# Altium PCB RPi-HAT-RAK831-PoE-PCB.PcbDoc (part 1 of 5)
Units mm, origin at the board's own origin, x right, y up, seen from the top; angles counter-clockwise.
Board outline 65 x 56 mm, 2 copper layers (Top Layer, Bottom Layer); 9 components, 14 nets, 9110 pads, 249 vias.
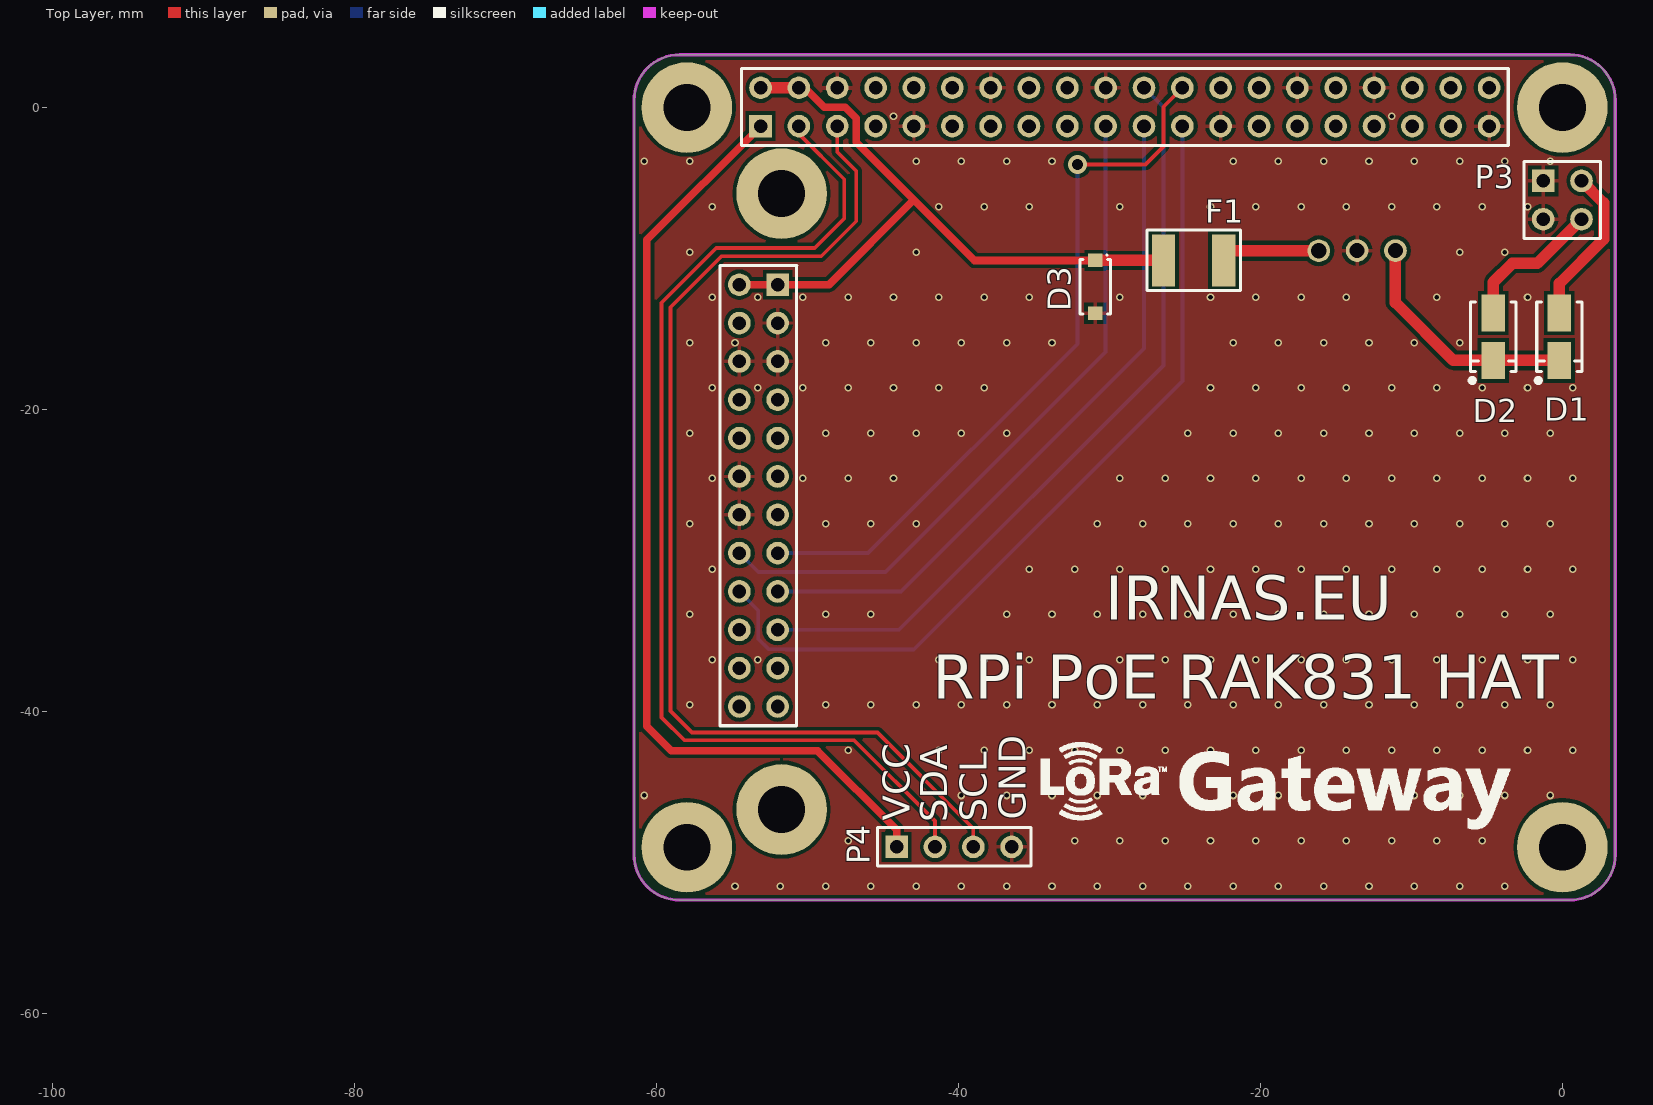
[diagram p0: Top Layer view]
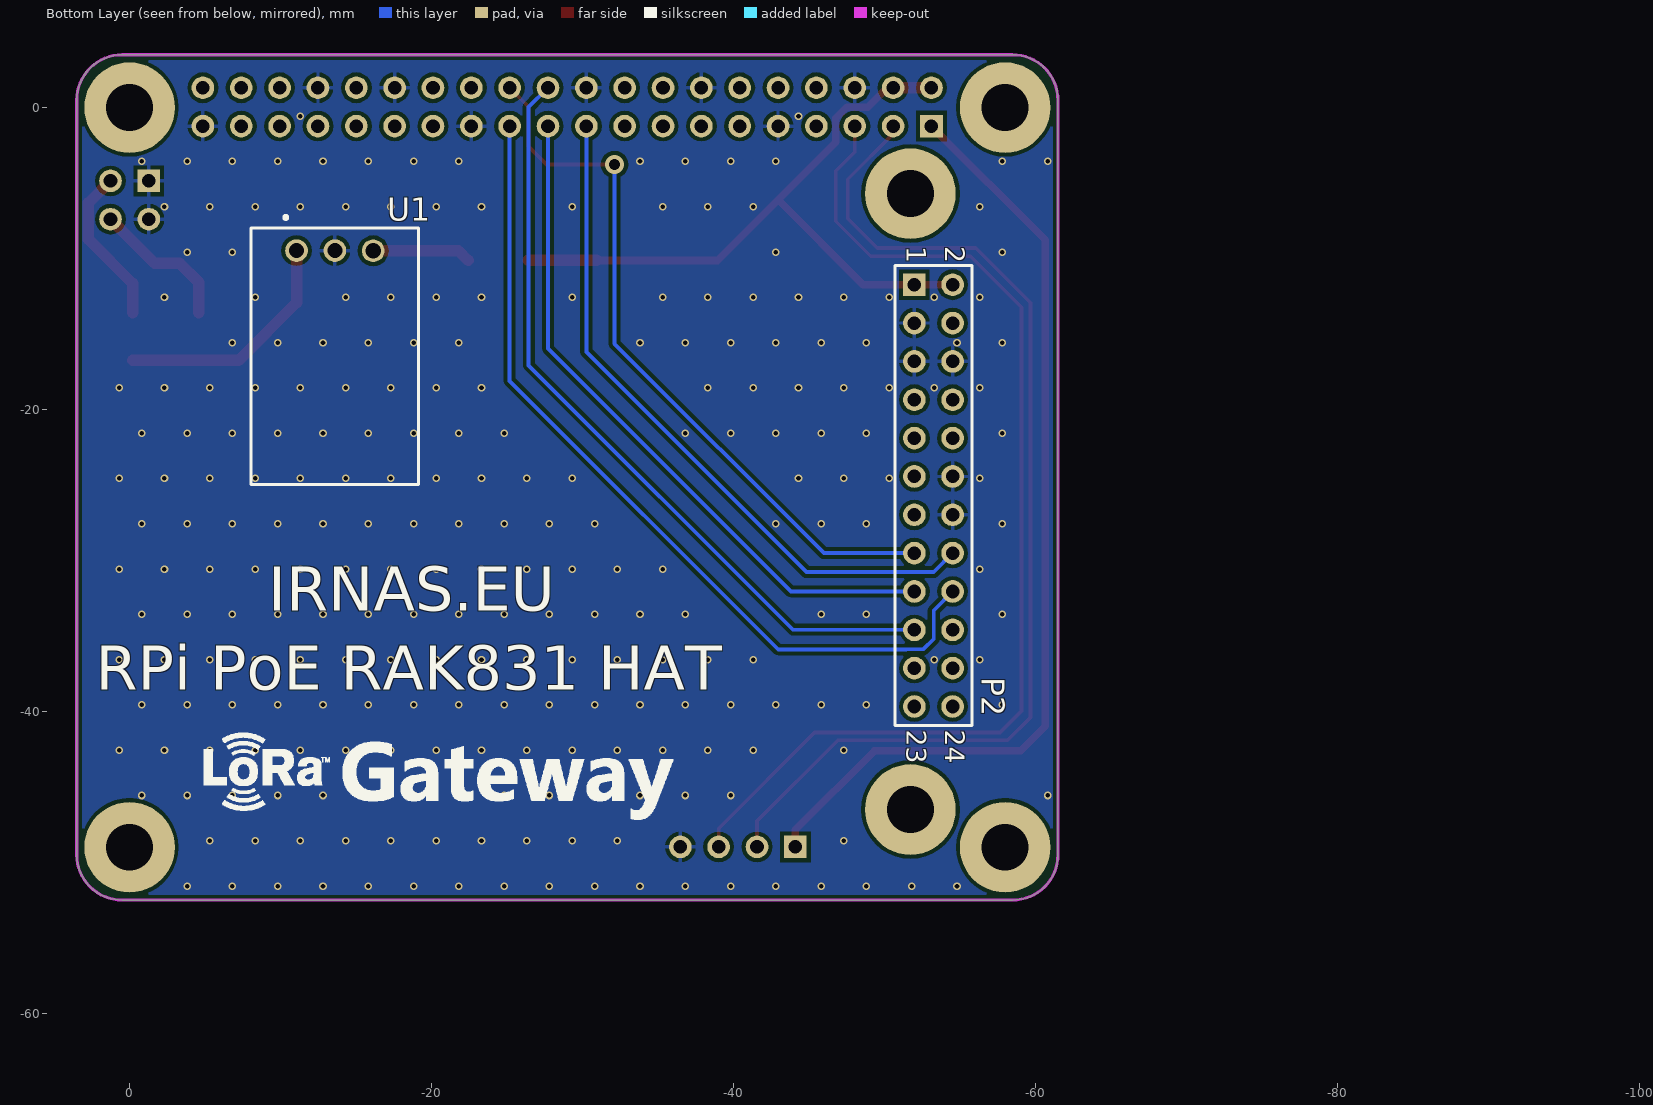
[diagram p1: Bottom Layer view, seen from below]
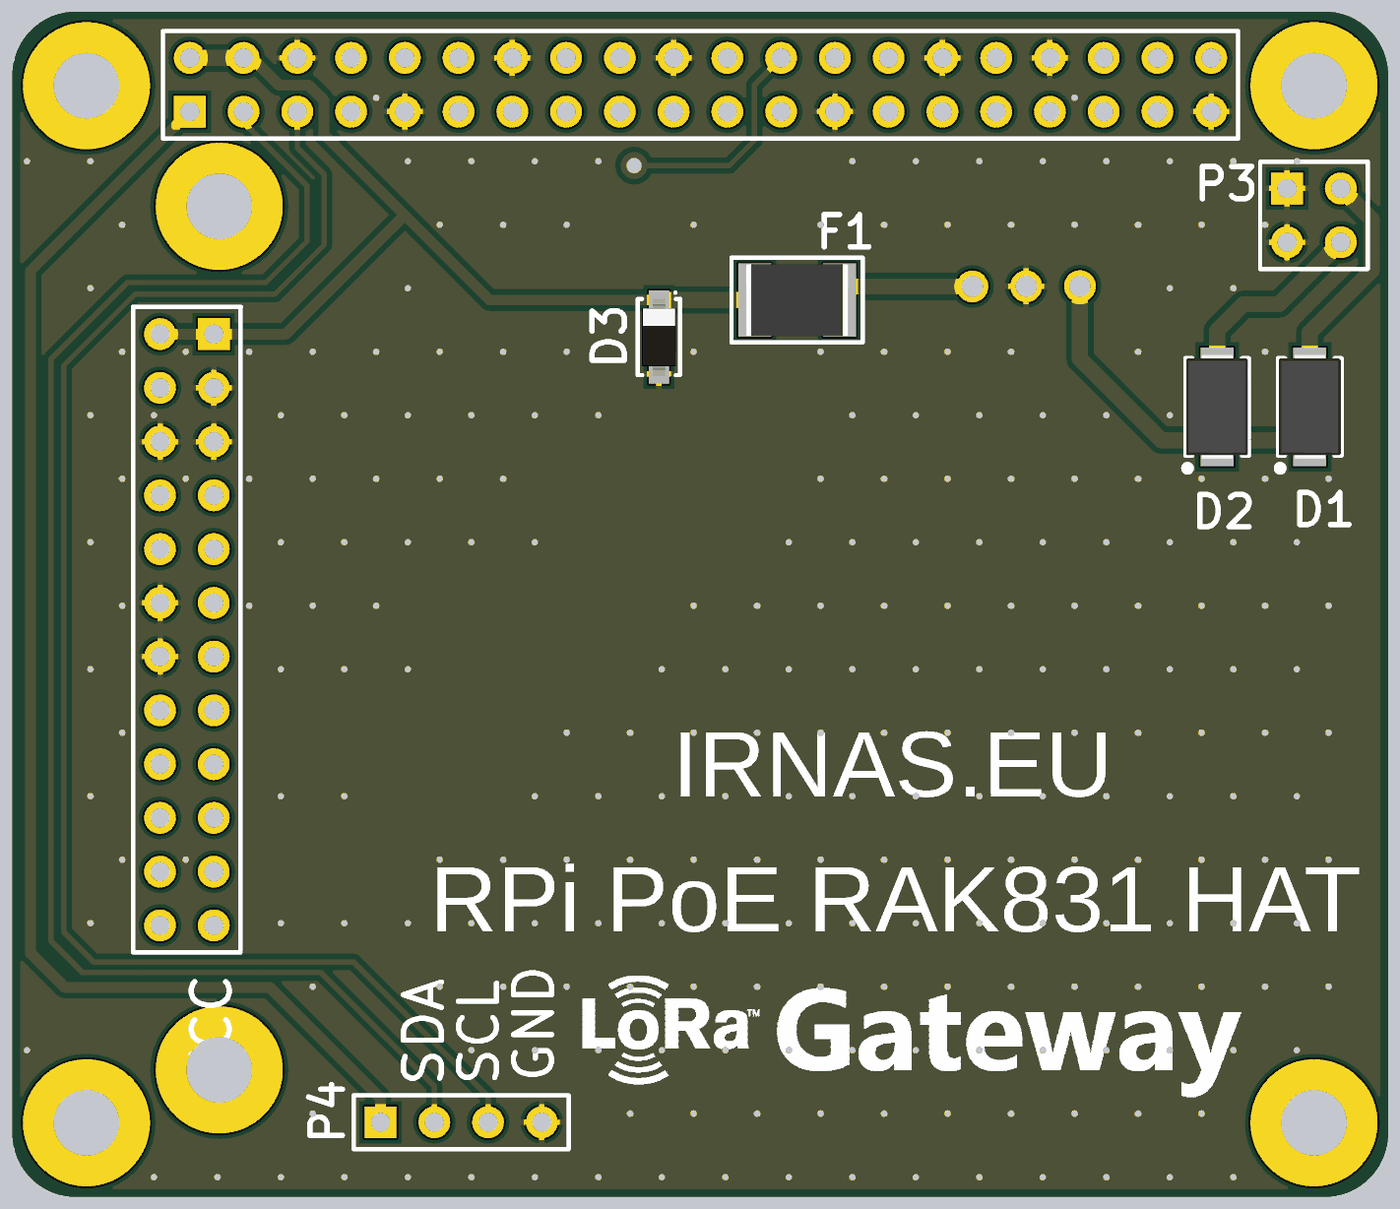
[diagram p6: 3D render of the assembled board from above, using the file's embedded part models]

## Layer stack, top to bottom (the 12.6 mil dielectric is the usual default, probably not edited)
Top Solder: solder mask 0.0102, Solder Resist, Dk 3.5
Top Layer: signal copper 0.0356
Dielectric 1: dielectric 0.32, FR-4, Dk 4.8
Bottom Layer: signal copper 0.0356
Bottom Solder: solder mask 0.0102, Solder Resist, Dk 3.5

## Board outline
-61.5,-49.5 ccw(c-58.5,-49.5) -58.5,-52.5 0.5,-52.5 ccw(c0.5,-49.5) 3.5,-49.5 3.5,0.5 ccw(c0.5,0.5) 0.5,3.5 -58.5,3.5 ccw(c-58.5,0.5) -61.5,0.5

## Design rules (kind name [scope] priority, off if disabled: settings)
BoardOutlineClearance [All] p1: gap=0.254 ignorepadtopadclearanceinfootprint=FALSE except(0: Arc-SplitContinuation Track-SplitContinuation SMDPad-SplitContinuation THPad-SplitContinuation Via-SplitContinuation Fill-SplitContinuation Poly-SplitContinuation Region-SplitContinuation Text-SplitContinuation)
Clearance [All] p1: gap=0.254 ignorepadtopadclearanceinfootprint=FALSE except(0: Arc-Hole Track-Hole SMDPad-Hole THPad-Hole Via-Hole Fill-Hole Poly-Hole Region-Hole Text-Hole)
ComponentClearance [All] p1: gap=0.01 collisioncheckmode=3 verticalgap=0.254 showdistances=FALSE
HoleSize [All] p1: absolutevalues=TRUE maxlimit=5 minlimit=0.025 maxpercent=80.000 minpercent=20.000
PolygonConnect PolygonConnect_t [IsVia vs OnLayer('Top Layer')] p1: connectstyle=Direct reliefconductorwidth=0.254 reliefentries=4 polygonreliefangle="90 Angle" airgapwidth=0.254
PolygonConnect PolygonConnect_b [IsVia vs OnLayer('Bottom Layer')] p2: connectstyle=Direct reliefconductorwidth=0.254 reliefentries=4 polygonreliefangle="90 Angle" airgapwidth=0.254
PolygonConnect [All] p3: connectstyle=Relief reliefconductorwidth=0.254 reliefentries=4 polygonreliefangle="90 Angle" airgapwidth=0.254
RoutingVias [All] p1: holewidth=0.711 width=1.27 viastyle="Through Hole" minholewidth=0.711 minwidth=1.27 maxholewidth=0.711 maxwidth=1.27
SolderMaskExpansion [All] p1: expansion=0.102
Width [All] p1: maxlimit=1.27 minlimit=0.254 preferedwidth=0.254 minimp=50.000000 maximp=50.000000 favimp=50.000000
28 further rules are at their usual default settings.

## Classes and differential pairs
component class PAGE2-RPI,RAK831,POWER: D1 D2 D3 F1 P2 P3 P4 U1

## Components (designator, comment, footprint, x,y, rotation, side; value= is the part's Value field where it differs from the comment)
D1 "MRA4007T3G" DIOM4326X24N_1 -0.2,-15.175 r90 top
D2 "MRA4007T3G" DIOM4326X24N_1 -4.575,-15.175 r90 top
D3 "BZT52C6V2" SOD123 -30.95,-11.875 r270 top
F1 "3A" Chip2PinSM127P600-8N -24.425,-10.125 r180 top
P1 "Header 20X2" HDR2X20 -53.118,-1.227 r0 top locked
P2 "Header 12X2" HDR2X12 -51.985,-11.735 r270 bottom
P3 "Header 2X2" HDR2X2 -1.275,-4.855 r270 top locked
P4 "Header 4" HDR1X4 -44.105,-48.975 r0 top
U1 "OKI-78SR-5" DC-DC -13.55,-23.975 r0 bottom

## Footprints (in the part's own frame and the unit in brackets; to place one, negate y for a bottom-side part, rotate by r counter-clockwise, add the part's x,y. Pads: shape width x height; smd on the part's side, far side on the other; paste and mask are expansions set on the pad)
Chip2PinSM127P600-8N [mm]
  rect 1.55x3.45 smd: 1(-2,0) 2(2,0)
  silkscreen extent -3.1,-2 3.1,2, body extent -2.41,-1.7 2.42,1.71, height 1.94
DC-DC [mm]
  round 1.501 hole 1: 1(2.49,-14.5) 2(-0.05,-14.5)
  round 1.5 hole 1: 3(-2.59,-14.49)
  silkscreen extent -5.6,-16.8 5.5,1, body extent -5.6,-15.98 5.49,0.96, height 7.6
DIOM4326X24N_1 [mm] "Molded Diode, 2-Leads, Body 4.31x2.60mm, IPC Medium Density"
  rect 2.45x1.55 smd: 1(-1.575,0) 2(1.575,0)
  silkscreen extent -3.05,-1.5 2.3,1.55, body extent -2.5,-1.46 2.51,1.46, height 2.41
HDR1X4 [mm] "Connector; Header; 4 Position"
  rect 1.5x1.5 hole 0.9: 1(0,0)
  round 1.5 hole 0.9: 2(2.54,0) 3(5.08,0) 4(7.62,0)
  silkscreen extent -1.27,-1.27 8.89,1.27
HDR2X2 [mm] "Connector; Header; 2x2 Position"
  rect 1.5x1.5 hole 0.9: 1(0,0)
  round 1.5 hole 0.9: 2(0,2.54) 3(2.54,0) 4(2.54,2.54)
  silkscreen extent -1.27,-1.27 3.81,3.81
HDR2X12 [mm] "Connector; Header; 12x2 Position"
  rect 1.5x1.5 hole 0.9: 1(0,0)
  round 1.5 hole 0.9: 2(0,2.54) 3(2.54,0) 4(2.54,2.54) 5(5.08,0) 6(5.08,2.54) 7(7.62,0) 8(7.62,2.54) 9(10.16,0) 10(10.16,2.54) 11(12.7,0) 12(12.7,2.54) 13(15.24,0) 14(15.24,2.54) 15(17.78,0) 16(17.78,2.54) 17(20.32,0) 18(20.32,2.54) 19(22.86,0) 20(22.86,2.54) 21(25.4,0) 22(25.4,2.54) 23(27.94,0) 24(27.94,2.54)
  silkscreen extent -1.27,-1.27 29.21,3.81
HDR2X20 [mm] "Connector; Header; 20x2 Position"
  rect 1.5x1.5 hole 0.9: 1(0,0)
  round 1.5 hole 0.9: 2(0,2.54) 3(2.54,0) 4(2.54,2.54) 5(5.08,0) 6(5.08,2.54) 7(7.62,0) 8(7.62,2.54) 9(10.16,0) 10(10.16,2.54) 11(12.7,0) 12(12.7,2.54) 13(15.24,0) 14(15.24,2.54) 15(17.78,0) 16(17.78,2.54) 17(20.32,0) 18(20.32,2.54) 19(22.86,0) 20(22.86,2.54) 21(25.4,0) 22(25.4,2.54) 23(27.94,0) 24(27.94,2.54) 25(30.48,0) 26(30.48,2.54) 27(33.02,0) 28(33.02,2.54) 29(35.56,0) 30(35.56,2.54) 31(38.1,0) 32(38.1,2.54) 33(40.64,0) 34(40.64,2.54) 35(43.18,0) 36(43.18,2.54) 37(45.72,0) 38(45.72,2.54) 39(48.26,0) 40(48.26,2.54)
  silkscreen extent -1.27,-1.27 49.53,3.81
SOD123 [mm] "SODFL, 2-Leads, Body 1.55x3.70mm, IPC Medium Density"
  rect 0.9x0.95 smd: 1(-1.75,0) 2(1.75,0)
  silkscreen extent -2.15,-1 1.8,1, body extent -1.85,-0.8 1.85,0.8, height 1.27

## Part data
D1 D2: "ON SEMICONDUCTOR - MRA4007T3G - DIODE, STANDARD, 1A, 1KV, SMA", Manufacturer="ON SEMICONDUCTOR", Supplier Part Number 1=1459137
D3: "DIODES INC. - BZT52C6V2 - DIODE, ZENER, 6.2V, 0.5W, SOD-123", Diode Case Style=SOD-123, Manufacturer="DIODES INC.", Operating Temperature Max=150, Operating Temperature Min=-65, Operating Temperature Range="-65°C to +150°C<!--FANDB--><div class{}\"features-and-benefits-container\"><div class{}\"features-and-benefits-desc-container\"><span class{}\"features-and-benefits-container-desc\">Zener Single Diode, 6.2 V, 500 mW, SOD-123, 6 %, 2 Pins, 150 °C</span></div><div class{}\"features-and-benefits-description\"><span class{}\"features-benefits-value\">The BZT52C6V2 is a surface mount Zener Diode with moulded plastic case, matte tin annealed over Alloy 42 lead frame (lead-free plating) terminals and cathode band polarity. It is ideally suited for automated assembly processes.</span></div><div class{}\"features-and-benefits-list\"><ul class{}\"features-and-benefits-list-list\"><li class{}\"features-and-benefits-list-item\">Planar die construction</li><li class{}\"features-and-benefits-list-item\">500mW Power dissipation</li><li class{}\"features-and-benefits-list-item\">General purpose, medium current</li><li class{}\"features-and-benefits-list-item\">Totally lead-free</li><li class{}\"features-and-benefits-list-item\">Halogen and antimony-free - Green device</li><li class{}\"features-and-benefits-list-item\">Qualified to AEC-Q101 standards for high reliability</li></ul></div><div class{}\"features-and-benefits-applications\"><ul class{}\"features-and-benefits-value\"><li class{}\"features-and-benefits-list-item\">Automation & Process Control</li></ul></div></div>", Power Dissipation Pd=500, Supplier Part Number 1=1902438, Zener Tolerance ±=6%, Zener Voltage Vz Typ=6.2
F1: library part "PTC FUSE 3A", "LITTELFUSE - MINISMDC150F/24-2 - POLYSWITCH, SMD, 1812, 1.5A", Manufacturer=LITTELFUSE, Manufacturer Part Number=MINISMDC150F/24-2, Supplier Part Number 1=1345929
P1: "Header, 20-Pin, Dual row"
P2: "Header, 12-Pin, Dual row"
P3: "Header, 2-Pin, Dual row"
P4: "Header, 4-Pin"
U1: library part OKI-78SR-5/1.5-W36H-C, "Non-Isolated DC/DC Converters 7.5W 24V 5Vout 1.5A Horizontal Mount", Case/Package=SIP, Current - Output 1=1.5A, Manufacturer=Murata, Max Input Voltage=36V, Max Operating Temperature=85°C, Max Power Dissipation=8W, Min Input Voltage=7V, Min Operating Temperature=-40°C, Nominal Input Voltage=24V, Output Power=7.5W, Output Voltage=5V, Package Quantity=100, Supplier Part Number 1=2766437

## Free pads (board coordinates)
  round 6 hole 3.1: 0(-58,-49) 0(-58,0) 0(-51.725,-46.5) 0(-51.725,-5.7) 0(0,-49) 0(0,0)
  round 0.008 on Mech16: 1(-98.413,-61.398) 1(-98.411,-61.431) 1(-98.409,-62.446) 1(-98.406,-62.479) 1(-98.402,-62.408) 1(-98.398,-61.456) 1(-98.393,-61.371) 1(-98.383,-62.504) 1(-98.373,-61.468) 1(-98.371,-62.392) 1(-98.358,-61.359) 1(-98.345,-62.504) 1(-98.343,-61.466) 1(-98.329,-62.395) 1(-98.322,-61.363) 1(-98.314,-61.453) 1(-98.313,-62.486) 1(-98.307,-62.422) 1(-98.302,-61.392) 1(-98.301,-62.454) 1(-98.3,-61.424) 1(-98.26,-62.529) 1(-98.26,-62.124) 1(-98.26,-62.04) 1(-98.259,-61.971) 1(-98.259,-61.491) 1(-98.258,-62.405) 1(-98.258,-61.933) 1(-98.258,-61.893) 1(-98.258,-61.629) 1(-98.257,-62.362) 1(-98.257,-62.179) 1(-98.256,-62.46) 1(-98.256,-62.219) 1(-98.256,-61.844) 1(-98.244,-61.454) 1(-98.233,-61.751) 1(-98.229,-61.727) 1(-98.223,-61.821) 1(-98.218,-61.707) 1(-98.217,-61.614) 1(-98.21,-61.577) 1(-98.205,-62.532) 1(-98.205,-62.02) 1(-98.203,-61.688) 1(-98.2,-61.339) 1(-98.187,-61.673) 1(-98.183,-61.394) 1(-98.18,-61.626) 1(-98.179,-61.932) 1(-98.179,-61.906) 1(-98.178,-62.239) 1(-98.171,-61.657) 1(-98.169,-61.878) 1(-98.164,-61.849) 1(-98.163,-61.735) 1(-98.162,-62.428) 1(-98.158,-62.233) 1(-98.154,-61.571) 1(-98.147,-61.808) 1(-98.146,-62.314) 1(-98.145,-61.526) 1(-98.139,-62.532) 1(-98.139,-62.442) 1(-98.136,-61.769) 1(-98.135,-61.945) 1(-98.135,-61.891) 1(-98.125,-61.591) 1(-98.122,-62.275) 1(-98.114,-61.87) 1(-98.105,-61.973) 1(-98.103,-61.582) 1(-98.102,-61.934) 1(-98.083,-61.57) 1(-98.079,-61.934) 1(-98.078,-62.533) 1(-98.075,-62.23) 1(-98.074,-62.263) 1(-98.071,-61.408) 1(-98.064,-62.122) 1(-98.064,-62.085) 1(-98.063,-62.102) 1(-98.063,-61.327) 1(-98.062,-61.559) 1(-98.057,-61.934) 1(-98.048,-62.097) 1(-98.04,-61.406) 1(-98.037,-62.311) 1(-98.035,-61.934) 1(-98.034,-61.555) 1(-98.034,-61.619) 1(-98.034,-61.329) 1(-98.031,-62.096) 1(-98.023,-62.535) 1(-98.014,-62.311) 1(-98.004,-62.107) 1(-97.994,-62.31) 1(-97.994,-61.911) 1(-97.986,-62.186) 1(-97.986,-61.493) 1(-97.976,-61.331) 1(-97.975,-62.31) 1(-97.972,-61.424) 1(-97.962,-61.493) 1(-97.96,-62.502) 1(-97.943,-62.536) 1(-97.936,-61.493) 1(-97.934,-62.079) 1(-97.931,-62.11) 1(-97.924,-61.331) 1(-97.923,-61.424) 1(-97.917,-61.92) 1(-97.914,-61.604) 1(-97.911,-61.493) 1(-97.909,-62.197) 1(-97.896,-62.248) 1(-97.894,-62.39) 1(-97.886,-61.493) 1(-97.885,-61.928) 1(-97.883,-62.284) 1(-97.881,-62.534) 1(-97.88,-61.331) 1(-97.88,-62.42) 1(-97.873,-61.425) 1(-97.869,-62.222) 1(-97.867,-62.096) 1(-97.867,-61.52) 1(-97.861,-61.637) 1(-97.857,-61.767) 1(-97.856,-61.484) 1(-97.855,-62.49) 1(-97.853,-61.913) 1(-97.84,-61.933) 1(-97.828,-61.331) 1(-97.827,-61.652) 1(-97.826,-61.768) 1(-97.825,-62.334) 1(-97.824,-61.424) 1(-97.822,-61.504) 1(-97.802,-62.094) 1(-97.796,-62.534) 1(-97.795,-62.49) 1(-97.789,-61.637) 1(-97.787,-61.473) 1(-97.777,-62.138) 1(-97.776,-61.332) 1(-97.776,-62.195) 1(-97.775,-61.424) 1(-97.767,-61.658) 1(-97.762,-62.157) 1(-97.762,-61.797) 1(-97.746,-61.458) 1(-97.742,-62.533) 1(-97.736,-61.658) 1(-97.734,-62.413) 1(-97.731,-62.266) 1(-97.714,-61.975) 1(-97.711,-62.363) 1(-97.711,-61.935) 1(-97.711,-61.907) 1(-97.711,-61.879) 1(-97.711,-61.851) 1(-97.711,-61.54) 1(-97.709,-61.571) 1(-97.708,-61.812) 1(-97.708,-61.5) 1(-97.694,-61.456) 1(-97.683,-61.904) 1(-97.682,-62.533) 1(-97.682,-62.497) 1(-97.682,-62.357) 1(-97.68,-61.842) 1(-97.68,-62.393) 1(-97.68,-61.591) 1(-97.679,-62.282) 1(-97.678,-61.544) 1(-97.676,-61.512) 1(-97.638,-61.593) 1(-97.637,-61.672) 1(-97.636,-61.546) 1(-97.635,-62.317) 1(-97.61,-61.711) 1(-97.605,-61.912) 1(-97.602,-62.039) 1(-97.6,-61.77) 1(-97.597,-62.196) 1(-97.591,-62.171) 1(-97.59,-62.147) 1(-97.589,-62.115) 1(-97.582,-61.546) 1(-97.58,-61.97) 1(-97.578,-61.598) 1(-97.565,-62.236) 1(-97.557,-62.266) 1(-97.556,-61.961) 1(-97.535,-62.273) 1(-97.534,-61.961) 1(-97.515,-61.68) 1(-97.513,-62.28) 1(-97.512,-61.961) 1(-97.503,-61.547) 1(-97.491,-62.289) 1(-97.49,-61.961) 1(-97.462,-61.959) 1(-97.45,-61.546) 1(-97.438,-62.064) 1(-97.438,-61.737) 1(-97.418,-62.285) 1(-97.405,-61.605) 1(-97.402,-61.546) 1(-97.387,-62.211) 1(-97.377,-61.604) 1(-97.376,-61.97) 1(-97.376,-62.267) 1(-97.362,-62.064) 1(-97.36,-61.737) 1(-97.36,-61.546) 1(-97.356,-62.006) 1(-97.354,-61.891) 1(-97.349,-62.166) 1(-97.344,-61.684) 1(-97.341,-61.587) 1(-97.34,-61.634) 1(-97.338,-62.228) 1(-97.323,-61.93) 1(-97.323,-62.006) 1(-97.322,-62.288) 1(-97.322,-61.774) 1(-97.314,-61.885) 1(-97.311,-62.139) 1(-97.311,-62.063) 1(-97.298,-61.686) 1(-97.297,-61.546) 1(-97.293,-62.251) 1(-97.291,-62.104) 1(-97.29,-61.646) 1(-97.287,-62.177) 1(-97.286,-61.586) 1(-97.285,-61.796) 1(-97.283,-61.96) 1(-97.255,-61.776) 1(-97.235,-61.546) 1(-97.224,-61.808) 1(-97.22,-62.221) 1(-97.219,-62.084) 1(-97.219,-61.688) 1(-97.216,-62.286) 1(-97.211,-62) 1(-97.206,-61.588) 1(-97.198,-61.721) 1(-97.196,-62.17) 1(-97.195,-61.836) 1(-97.191,-62.124) 1(-97.186,-61.759) 1(-97.18,-61.546) 1(-97.174,-61.58) 1(-97.158,-62.126) 1(-97.157,-62.091) 1(-97.156,-61.998) 1(-97.146,-61.936) 1(-97.144,-62.286) 1(-97.144,-62.232) 1(-97.125,-61.793) 1(-97.123,-61.547) 1(-97.122,-61.829) 1(-97.097,-62.097) 1(-97.096,-62.195) 1(-97.094,-62.128) 1(-97.09,-61.998) 1(-97.084,-61.937) 1(-97.065,-61.547) 1(-97.063,-62.322) 1(-97.058,-61.675) 1(-97.036,-61.691) 1(-97.027,-62.283) 1(-97.019,-61.547) 1(-97.016,-61.835) 1(-97.016,-61.641) 1(-97.016,-61.657) 1(-97.015,-62.067) 1(-97.015,-61.973) 1(-97.013,-62.233) 1(-97.012,-62.32) 1(-97.002,-61.904) 1(-96.996,-61.799) 1(-96.991,-61.762) 1(-96.988,-62.026) 1(-96.987,-62.103) 1(-96.984,-61.544) 1(-96.963,-62.081) 1(-96.962,-62.276) 1(-96.96,-61.976) 1(-96.957,-61.858) 1(-96.956,-61.906) 1(-96.956,-62.323) 1(-96.947,-61.773) 1(-96.945,-61.693) 1(-96.944,-61.612) 1(-96.942,-61.546) 1(-96.941,-62.233) 1(-96.939,-62.14) 1(-96.919,-61.445) 1(-96.907,-61.977) 1(-96.907,-61.905) 1(-96.903,-62.037) 1(-96.9,-62.323) 1(-96.9,-62.102) 1(-96.898,-61.671) 1(-96.895,-61.333) 1(-96.893,-61.782) 1(-96.891,-61.828) 1(-96.89,-62.278) 1(-96.885,-61.586) 1(-96.881,-61.635) 1(-96.879,-62.23) 1(-96.872,-62.169) 1(-96.864,-61.544) 1(-96.862,-61.696) 1(-96.851,-61.785) 1(-96.849,-62.037) 1(-96.849,-61.982) 1(-96.848,-62.322) 1(-96.847,-61.869) 1(-96.847,-61.617) 1(-96.845,-62.282) 1(-96.84,-62.23) 1(-96.839,-62.124) 1(-96.829,-61.939) 1(-96.829,-61.831) 1(-96.824,-61.917) 1(-96.824,-61.666) 1(-96.818,-61.544) 1(-96.808,-61.333) 1(-96.804,-61.591) 1(-96.791,-61.79) 1(-96.785,-61.444) 1(-96.78,-61.545) 1(-96.778,-62.322) 1(-96.778,-61.63) 1(-96.73,-61.59) 1(-96.71,-62.18) 1(-96.71,-61.619) 1(-96.709,-62.224) 1(-96.709,-62.017) 1(-96.709,-61.824) 1(-96.708,-61.877) 1(-96.708,-61.769) 1(-96.707,-62.122) 1(-96.707,-62.069) 1(-96.707,-61.561) 1(-96.706,-62.276) 1(-96.706,-61.956) 1(-96.706,-61.703) 1(-96.705,-62.317) 1(-96.682,-61.633) 1(-96.676,-62.28) 1(-96.676,-62.224) 1(-96.673,-62.325) 1(-96.673,-61.999) 1(-96.672,-62.166) 1(-96.671,-61.583) 1(-96.665,-61.873) 1(-96.662,-61.813) 1(-96.662,-61.699) 1(-96.651,-61.957) 1(-96.643,-61.633) 1(-96.642,-62.28) 1(-96.636,-61.595) 1(-96.632,-62.329) 1(-96.627,-62.224) 1(-96.624,-62.005) 1(-96.614,-61.849) 1(-96.609,-62.431) 1(-96.609,-61.422) 1(-96.607,-61.7) 1(-96.605,-62.159) 1(-96.603,-61.38) 1(-96.6,-62.482) 1(-96.597,-62.28) 1(-96.596,-61.63) 1(-96.596,-61.453) 1(-96.591,-62.4) 1(-96.59,-62.006) 1(-96.583,-62.221) 1(-96.58,-62.502) 1(-96.578,-61.802) 1(-96.576,-61.844) 1(-96.575,-61.36) 1(-96.567,-61.468) 1(-96.562,-61.748) 1(-96.557,-62.393) 1(-96.548,-62.505) 1(-96.548,-61.625) 1(-96.547,-61.703) 1(-96.546,-62.288) 1(-96.543,-62.213) 1(-96.542,-61.99) 1(-96.542,-62.024) 1(-96.541,-61.809) 1(-96.54,-61.844) 1(-96.535,-62.152) 1(-96.534,-61.357) 1(-96.527,-62.395) 1(-96.527,-61.469) 1(-96.525,-62.289) 1(-96.519,-62.495) 1(-96.516,-62.25) 1(-96.516,-61.625) 1(-96.514,-61.703) 1(-96.514,-62.213) 1(-96.514,-61.668) 1(-96.509,-61.759) 1(-96.508,-62.024) 1(-96.508,-61.99) 1(-96.507,-61.844) 1(-96.507,-61.372) 1(-96.505,-62.413) 1(-96.503,-61.811) 1(-96.503,-61.439) 1(-96.5,-62.474) 1(-96.496,-61.405) 1(-96.496,-62.442) 1(-96.474,-62.29) 1(-96.472,-61.988) 1(-96.472,-61.842) 1(-96.472,-61.718) 1(-96.471,-62.204) 1(-96.468,-62.024) 1(-96.466,-61.811) 1(-96.461,-61.659) 1(-94.737,-62.532) 1(-94.704,-61.973) 1(-94.344,-61.458) 1(-94.313,-61.975) 1(-94.292,-61.456) 1(-94.281,-61.904) 1(-94.28,-62.533) 1(-94.28,-62.497) 1(-94.28,-62.357) 1(-94.278,-61.842) 1(-94.278,-62.393) 1(-94.274,-61.512) 1(-94.18,-61.546) 1(-94.101,-61.547) 1(-94.048,-61.546) 1(-94,-61.546) 1(-93.554,-62.323) 1(-93.498,-62.323) 1(-93.462,-61.544) 1(-93.446,-62.322) 1(-93.416,-61.544) 1(-93.378,-61.545) 1(-93.376,-62.322) 1(-93.306,-62.122) 1(-93.306,-61.561)
  round 5.2 on Mech5: 1(-51.725,-46.5) 1(-51.725,-5.7)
